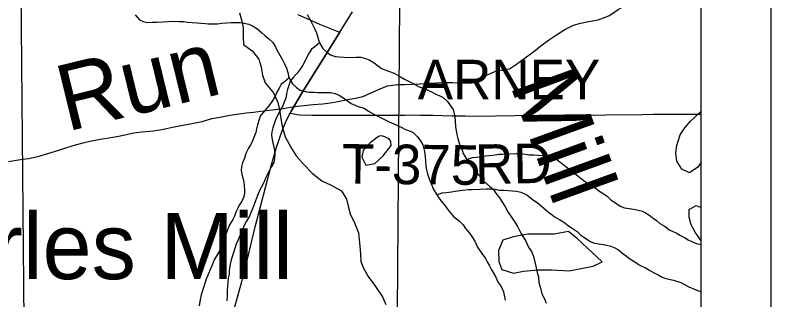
# Model space of a CAD drawing. Extents: x -21.1 to 50.3, y -4.9 to 22.1.
# Drawn here: x 7.916 to 9, y 17.651 to 18.059 of the extents above; entities that cross this region are included whole.
import ezdxf

# ---------------------------------------------------------------- set-up
doc = ezdxf.new("R2010")
doc.units = 0
for name, color, linetype in [('GM_X_Corporation', 7, 'Continuous'), ('GM_X_County', 7, 'Continuous'), ('GM_X_County_Road', 7, 'Continuous'), ('GM_X_Major_Lake', 7, 'Continuous'), ('GM_X_Major_Lake_Text', 7, 'Continuous'), ('GM_X_Minor_Lake', 7, 'Continuous'), ('GM_X_Minor_River', 7, 'Continuous'), ('GM_X_Minor_River_Text', 7, 'Continuous'), ('GM_X_Rail_Line_Text', 7, 'Continuous'), ('GM_X_Section', 7, 'Continuous'), ('GM_X_Township_Road', 7, 'Continuous'), ('GM_X_Township_Road_Text', 7, 'Continuous'), ('SH_Cut_Line', 7, 'Continuous'), ('SH_Data', 7, 'Continuous')]:
    doc.layers.add(name, color=color, linetype=linetype)

msp = doc.modelspace()

# ---------------------------------------------------------------- linework, layer by layer
at = {"layer": 'GM_X_Corporation'}
msp.add_lwpolyline([(8.9, 17.418), (8.9, 18.4235), (7.9213, 18.4125), (7.9303, 17.4089)], close=True, dxfattribs=at)
at = {"layer": 'GM_X_County'}
msp.add_lwpolyline([(8.9, 14.7464), (8.9, 20.9), (2.1, 20.9), (2.1, 14.1), (8.8932, 14.1)], dxfattribs=at)
at = {"layer": 'GM_X_County_Road'}
for points in [[(8.3818, 18.035), (8.4, 18.0643)], [(8.3107, 17.9188), (8.3121, 17.9215), (8.3278, 17.9484), (8.3572, 17.9959), (8.377, 18.0274), (8.3818, 18.035)], [(8.2266, 17.6235), (8.2411, 17.6773), (8.2487, 17.7073), (8.2605, 17.7556), (8.2721, 17.8008), (8.2833, 17.8429), (8.291, 17.8697), (8.2991, 17.8933), (8.305, 17.9077), (8.3107, 17.9188)]]:
    msp.add_lwpolyline(points, dxfattribs=at)
at = {"layer": 'GM_X_Major_Lake'}
for points in [[(8.2379, 18.0629), (8.2406, 18.0527), (8.2432, 18.0417), (8.2432, 18.0284), (8.2436, 18.017), (8.2561, 18.0083), (8.2655, 17.9962), (8.2689, 17.9848), (8.2708, 17.9731), (8.2746, 17.9624), (8.2864, 17.948), (8.2928, 17.934), (8.2951, 17.9241), (8.2973, 17.9105), (8.2996, 17.8976), (8.3034, 17.8847), (8.3121, 17.8691), (8.3189, 17.8574), (8.3299, 17.8452), (8.342, 17.8327), (8.356, 17.8217), (8.3693, 17.8153), (8.3841, 17.8073), (8.3913, 17.7952), (8.3935, 17.7853), (8.3966, 17.774), (8.403, 17.7611), (8.4083, 17.747), (8.4102, 17.7326), (8.4113, 17.7167), (8.4121, 17.7057), (8.4155, 17.6962), (8.4223, 17.6841), (8.4329, 17.67), (8.4431, 17.6549), (8.4477, 17.6439)], [(8.9, 17.8485), (8.8951, 17.8411), (8.8833, 17.8332), (8.8723, 17.8382), (8.8651, 17.85), (8.8637, 17.8618), (8.8652, 17.8724), (8.8698, 17.8876), (8.8767, 17.8975), (8.8847, 17.9073), (8.8973, 17.9186), (8.9, 17.9214)], [(8.4549, 17.8778), (8.4545, 17.8792), (8.4532, 17.8809), (8.4513, 17.8824), (8.4491, 17.8834), (8.4462, 17.8845), (8.4436, 17.8856), (8.4399, 17.8862), (8.4373, 17.8853)], [(8.4373, 17.8853), (8.4251, 17.8763), (8.4151, 17.865), (8.4131, 17.8555), (8.4191, 17.8441), (8.432, 17.8463), (8.4438, 17.8575), (8.4553, 17.8722), (8.4549, 17.8778)], [(8.9, 17.7354), (8.8979, 17.7385), (8.8914, 17.748), (8.8857, 17.7586), (8.8827, 17.7696), (8.8827, 17.7803), (8.893, 17.786), (8.9, 17.7832)]]:
    msp.add_lwpolyline(points, dxfattribs=at)
at = {"layer": 'GM_X_Minor_Lake'}
for points in [[(8.7223, 17.739), (8.7099, 17.749), (8.6893, 17.7451), (8.6681, 17.7449), (8.6514, 17.7451), (8.6305, 17.7411), (8.6156, 17.7363), (8.6094, 17.7216), (8.6096, 17.7056), (8.614, 17.6942), (8.6307, 17.6891), (8.6451, 17.692), (8.666, 17.6937), (8.6858, 17.6938), (8.7108, 17.6924), (8.7302, 17.6964), (8.745, 17.6993), (8.758, 17.7053)], [(8.758, 17.7053), (8.7223, 17.739)]]:
    msp.add_lwpolyline(points, dxfattribs=at)
at = {"layer": 'GM_X_Minor_River'}
for points in [[(8.6826, 18.0245), (8.6925, 18.0312), (8.7044, 18.0386), (8.7167, 18.0449), (8.727, 18.0478), (8.7388, 18.0502), (8.7525, 18.0527), (8.7678, 18.0585), (8.7812, 18.0675), (8.7943, 18.0752), (8.8076, 18.0807), (8.8206, 18.0828), (8.832, 18.083), (8.8456, 18.0824), (8.8555, 18.0827), (8.8677, 18.0836), (8.8772, 18.0846), (8.8883, 18.0875), (8.8978, 18.0927), (8.9, 18.0944)], [(8.0884, 18.0596), (8.0946, 18.0524), (8.0995, 18.0502), (8.1052, 18.049), (8.1128, 18.0491), (8.1193, 18.0491), (8.1281, 18.0496), (8.1361, 18.0504), (8.1425, 18.0508), (8.1509, 18.0504), (8.1578, 18.0501), (8.1627, 18.0494), (8.1772, 18.0483), (8.1825, 18.048), (8.1886, 18.0472), (8.1936, 18.0469), (8.2065, 18.0469), (8.2126, 18.0477), (8.219, 18.0482), (8.2259, 18.0486), (8.232, 18.049), (8.2388, 18.0486), (8.2445, 18.0479), (8.251, 18.0464), (8.2564, 18.0438), (8.2625, 18.04), (8.2698, 18.034), (8.2747, 18.0298), (8.2797, 18.0253), (8.2851, 18.0204), (8.2889, 18.0147), (8.2916, 18.0098), (8.2958, 18.0018), (8.2993, 17.9954), (8.3024, 17.9897), (8.3051, 17.9833), (8.307, 17.9768), (8.3082, 17.9719), (8.3105, 17.9666), (8.3139, 17.9609), (8.3197, 17.9556), (8.325, 17.9519), (8.3319, 17.9496), (8.3376, 17.9489), (8.3448, 17.9486), (8.3502, 17.9482), (8.3616, 17.9483), (8.3688, 17.9483), (8.3753, 17.9468), (8.3806, 17.9446), (8.3875, 17.9404), (8.3982, 17.9325), (8.4081, 17.9284), (8.4165, 17.9258), (8.423, 17.9216), (8.4314, 17.9167), (8.4429, 17.9111), (8.4524, 17.9062), (8.4593, 17.9036), (8.4707, 17.8983), (8.4761, 17.8953), (8.4818, 17.8931), (8.4868, 17.8908), (8.4925, 17.8852), (8.4963, 17.8802), (8.5009, 17.8734), (8.5033, 17.8636), (8.5041, 17.8564), (8.5045, 17.8491), (8.5053, 17.8427), (8.5061, 17.8374), (8.5076, 17.8317), (8.5107, 17.8218), (8.5134, 17.8169), (8.5154, 17.8101), (8.5207, 17.8017), (8.5273, 17.7923), (8.5326, 17.7855), (8.5376, 17.779), (8.5449, 17.7703), (8.5533, 17.7636), (8.5587, 17.7586), (8.5621, 17.7533), (8.5675, 17.7465), (8.5709, 17.7416), (8.5752, 17.7348), (8.5794, 17.7265), (8.5855, 17.7174), (8.5905, 17.7102), (8.5932, 17.7053)], [(8.3349, 18.0603), (8.3391, 18.0524), (8.3426, 18.0459), (8.3456, 18.0402), (8.3483, 18.0338), (8.3503, 18.0274), (8.3515, 18.0224), (8.3538, 18.0171), (8.3572, 18.0114), (8.363, 18.0061), (8.3683, 18.0024), (8.3752, 18.0001), (8.3809, 17.9994), (8.3881, 17.9991), (8.3935, 17.9987), (8.4049, 17.9988), (8.4121, 17.9988), (8.4186, 17.9973), (8.4239, 17.9951), (8.4308, 17.9909), (8.4415, 17.983), (8.4514, 17.9789), (8.4598, 17.9763), (8.4663, 17.9721), (8.4747, 17.9673), (8.4862, 17.9616), (8.4957, 17.9567), (8.5026, 17.9541), (8.514, 17.9489), (8.5194, 17.9459), (8.5251, 17.9436), (8.53, 17.9413), (8.5358, 17.9357), (8.5396, 17.9308), (8.5442, 17.924), (8.5466, 17.9141), (8.5474, 17.9069), (8.5478, 17.8997), (8.5486, 17.8932), (8.5494, 17.8879), (8.5509, 17.8822), (8.554, 17.8723), (8.5567, 17.8674), (8.5587, 17.8606), (8.564, 17.8523), (8.5706, 17.8428), (8.5759, 17.836), (8.5809, 17.8296), (8.5882, 17.8209), (8.5966, 17.8141), (8.602, 17.8092), (8.6054, 17.8039), (8.6108, 17.7971), (8.6142, 17.7921), (8.6185, 17.7853), (8.6227, 17.777), (8.6288, 17.7679), (8.6338, 17.7607), (8.6365, 17.7558)], [(7.9065, 17.8494), (7.9237, 17.8522), (7.9351, 17.8535), (7.9484, 17.8564), (7.9629, 17.8607), (7.9789, 17.8658), (7.99, 17.8694), (8.0026, 17.873), (8.0137, 17.8763), (8.0232, 17.8784), (8.0384, 17.8812), (8.0506, 17.8833), (8.0617, 17.8854), (8.0716, 17.8872), (8.0864, 17.8903), (8.0979, 17.8921), (8.1138, 17.8933), (8.1264, 17.8951), (8.1416, 17.8986), (8.1542, 17.9011), (8.1672, 17.9036), (8.1843, 17.9067), (8.1984, 17.9111), (8.2098, 17.9128), (8.2239, 17.9156), (8.2342, 17.9173), (8.2472, 17.9191), (8.2578, 17.92), (8.2685, 17.9214), (8.2852, 17.9234), (8.3004, 17.9255), (8.3111, 17.9272), (8.321, 17.9289), (8.3305, 17.9299), (8.3435, 17.9313), (8.3575, 17.9322), (8.3686, 17.9335), (8.3788, 17.9353), (8.3926, 17.9381), (8.404, 17.9402), (8.4147, 17.9427), (8.4265, 17.9479), (8.4372, 17.9526), (8.4502, 17.9578), (8.4643, 17.9598), (8.4746, 17.96), (8.486, 17.9602), (8.4958, 17.9609), (8.5091, 17.9618), (8.5206, 17.9624), (8.5339, 17.9629), (8.5437, 17.9628), (8.5547, 17.9622), (8.5676, 17.9617), (8.5817, 17.9637), (8.5917, 17.9727), (8.6048, 17.979), (8.6158, 17.9807), (8.6253, 17.9824), (8.6353, 17.9891), (8.6495, 17.9996), (8.6599, 18.0074), (8.6703, 18.0156), (8.6826, 18.0245)], [(8.3526, 18.0198), (8.3458, 18.014), (8.3409, 18.0106), (8.3378, 18.0053), (8.3345, 17.9992), (8.3322, 17.9938), (8.3288, 17.9877), (8.3247, 17.9816), (8.3205, 17.9763), (8.3148, 17.9698), (8.3107, 17.9648), (8.3092, 17.9599), (8.3069, 17.9527), (8.3054, 17.9469), (8.3047, 17.9416), (8.3017, 17.9344), (8.2998, 17.9291), (8.2968, 17.9237), (8.2942, 17.9188), (8.2904, 17.9115), (8.2882, 17.9047), (8.2855, 17.8978), (8.284, 17.8921), (8.2837, 17.8872), (8.2845, 17.8811), (8.2857, 17.8762), (8.2872, 17.8701), (8.288, 17.8652), (8.2884, 17.8599), (8.2881, 17.8534), (8.287, 17.8481), (8.2839, 17.842), (8.2809, 17.837), (8.2783, 17.8321), (8.276, 17.8271), (8.2738, 17.8214), (8.2715, 17.8165), (8.267, 17.8088), (8.2636, 17.8005), (8.2606, 17.7928), (8.2587, 17.7875), (8.2572, 17.7826), (8.2546, 17.7769), (8.252, 17.7708), (8.2478, 17.7635), (8.2448, 17.7586), (8.2418, 17.751), (8.2396, 17.746), (8.2358, 17.7369), (8.2332, 17.7308), (8.2309, 17.7232), (8.2261, 17.7083), (8.2246, 17.7019), (8.2231, 17.6927), (8.2228, 17.6878), (8.2216, 17.6817), (8.2213, 17.676), (8.2206, 17.6703), (8.2202, 17.6635), (8.2203, 17.6559), (8.2199, 17.6494)], [(8.3093, 17.9693), (8.3025, 17.9635), (8.2976, 17.9601), (8.2946, 17.9547), (8.2912, 17.9486), (8.2889, 17.9433), (8.2855, 17.9372), (8.2814, 17.9311), (8.2772, 17.9258), (8.2715, 17.9193), (8.2674, 17.9143), (8.2659, 17.9094), (8.2636, 17.9021), (8.2621, 17.8964), (8.2614, 17.8911), (8.2584, 17.8839), (8.2565, 17.8785), (8.2535, 17.8732), (8.2509, 17.8683), (8.2471, 17.861), (8.2449, 17.8542), (8.2422, 17.8473), (8.2408, 17.8416), (8.2404, 17.8367), (8.2412, 17.8306), (8.2424, 17.8257), (8.2439, 17.8196), (8.2447, 17.8147), (8.2451, 17.8093), (8.2448, 17.8029), (8.2437, 17.7976), (8.2406, 17.7915), (8.2376, 17.7865), (8.235, 17.7816), (8.2327, 17.7766), (8.2305, 17.7709), (8.2282, 17.7659), (8.2237, 17.7583), (8.2203, 17.7499), (8.2173, 17.7423), (8.2154, 17.737), (8.214, 17.7321), (8.2113, 17.7263), (8.2087, 17.7202), (8.2045, 17.713), (8.2015, 17.7081), (8.1985, 17.7004), (8.1963, 17.6955), (8.1925, 17.6863), (8.1899, 17.6803), (8.1876, 17.6726), (8.1828, 17.6578), (8.1813, 17.6513), (8.1798, 17.6422)], [(8.5642, 17.8521), (8.572, 17.855), (8.5777, 17.8554), (8.5853, 17.8562), (8.5907, 17.8573), (8.6013, 17.8585), (8.6097, 17.8597), (8.615, 17.8598), (8.6257, 17.8602), (8.6348, 17.8606), (8.6416, 17.8607), (8.6477, 17.8599), (8.6535, 17.8588), (8.6599, 17.8589), (8.6725, 17.8578), (8.6786, 17.8571), (8.6847, 17.856), (8.6931, 17.8522), (8.7015, 17.8454), (8.708, 17.8409), (8.7137, 17.836), (8.721, 17.83), (8.726, 17.8262), (8.734, 17.8202), (8.7416, 17.8156), (8.7477, 17.8119), (8.7531, 17.8073), (8.7581, 17.8043), (8.7653, 17.7994), (8.771, 17.7938), (8.7772, 17.79), (8.784, 17.7851), (8.7901, 17.7829), (8.8, 17.7814), (8.8058, 17.7803), (8.8138, 17.7784), (8.8187, 17.7766), (8.8248, 17.7728), (8.831, 17.7679), (8.8359, 17.7645), (8.8409, 17.7603), (8.8482, 17.7558), (8.8543, 17.7513), (8.8592, 17.749), (8.8642, 17.7468), (8.8695, 17.7434), (8.876, 17.74), (8.8814, 17.737), (8.8875, 17.734), (8.8928, 17.7318), (8.9, 17.7303)], [(8.5209, 17.8016), (8.5287, 17.8044), (8.5344, 17.8049), (8.542, 17.8057), (8.5474, 17.8068), (8.558, 17.808), (8.5664, 17.8092), (8.5717, 17.8092), (8.5824, 17.8097), (8.5915, 17.8101), (8.5984, 17.8102), (8.6044, 17.8094), (8.6102, 17.8083), (8.6166, 17.8084), (8.6292, 17.8073), (8.6353, 17.8066), (8.6414, 17.8055), (8.6498, 17.8017), (8.6582, 17.7949), (8.6647, 17.7904), (8.6704, 17.7855), (8.6777, 17.7794), (8.6827, 17.7757), (8.6907, 17.7696), (8.6983, 17.7651), (8.7044, 17.7614), (8.7098, 17.7568), (8.7148, 17.7538), (8.722, 17.7489), (8.7278, 17.7432), (8.7339, 17.7395), (8.7408, 17.7346), (8.7469, 17.7323), (8.7568, 17.7309), (8.7625, 17.7298), (8.7705, 17.7279), (8.7754, 17.726), (8.7815, 17.7223), (8.7877, 17.7174), (8.7926, 17.714), (8.7976, 17.7098), (8.8049, 17.7053), (8.811, 17.7008), (8.8159, 17.6985), (8.8209, 17.6963), (8.8262, 17.6929), (8.8327, 17.6895), (8.8381, 17.6865), (8.8442, 17.6835), (8.8495, 17.6812), (8.8603, 17.679)], [(8.6365, 17.7558), (8.6396, 17.7501), (8.6423, 17.7452), (8.6484, 17.735), (8.6523, 17.7262), (8.6565, 17.7202), (8.6596, 17.713), (8.6623, 17.7008), (8.665, 17.6898), (8.6666, 17.6838), (8.6674, 17.6758), (8.6701, 17.6663), (8.6717, 17.6595), (8.6752, 17.6523), (8.6779, 17.6462)], [(8.5932, 17.7053), (8.5963, 17.6996), (8.599, 17.6947), (8.6051, 17.6844), (8.609, 17.6757), (8.6132, 17.6697), (8.6163, 17.6625), (8.619, 17.6503)], [(8.8603, 17.679), (8.8707, 17.6756), (8.8821, 17.6695), (8.8916, 17.6658), (8.9, 17.6623)]]:
    msp.add_lwpolyline(points, dxfattribs=at)
at = {"layer": 'GM_X_Rail_Line_Text'}
msp.add_lwpolyline([(8.9, 16.4052), (8.9, 20.435)], dxfattribs=at)
at = {"layer": 'GM_X_Section'}
msp.add_lwpolyline([(7.4621, 18.1346), (8.4678, 18.1394), (8.46, 17.1311), (8.3964, 17.1315), (7.4753, 17.1323)], close=True, dxfattribs=at)
at = {"layer": 'GM_X_Township_Road'}
for points in [[(8.3217, 18.0605), (8.3527, 18.0465), (8.3671, 18.0407), (8.3789, 18.0361), (8.3818, 18.035)], [(8.3818, 18.035), (8.377, 18.0274), (8.3572, 17.9959), (8.3278, 17.9484), (8.3121, 17.9215), (8.3107, 17.9188)], [(8.3107, 17.9188), (8.3162, 17.9176), (8.3205, 17.9167), (8.3246, 17.9163), (8.3415, 17.9159), (8.3694, 17.9159), (8.3974, 17.9158), (8.4191, 17.9156), (8.4377, 17.9157), (8.4563, 17.9158), (8.4749, 17.9159), (8.4873, 17.9161), (8.4966, 17.916), (8.5152, 17.9156), (8.5431, 17.915), (8.5617, 17.9147), (8.5804, 17.9145), (8.6052, 17.9147), (8.6331, 17.9152), (8.6672, 17.9159), (8.692, 17.916), (8.7137, 17.9157), (8.7292, 17.9157), (8.7633, 17.9162), (8.8161, 17.9169), (8.8316, 17.9171), (8.847, 17.9171), (8.8778, 17.9171), (8.9, 17.9174)]]:
    msp.add_lwpolyline(points, dxfattribs=at)
at = {"layer": 'SH_Cut_Line'}
msp.add_lwpolyline([(8.9, 16.4052), (8.9, 20.9), (2.1, 20.9)], dxfattribs=at)
at = {"layer": 'SH_Data'}
msp.add_line((9, 21), (9, 14), dxfattribs=at)

# ---------------------------------------------------------------- texts
at = {"layer": 'GM_X_Major_Lake_Text'}
for s, height, rotation, p in [('Mill', 0.09473, 289.9962, (8.6253, 17.9601)), ('Charles Mill', 0.094718, 359.9981, (7.6527, 17.6805))]:
    msp.add_text(s, height=height, rotation=rotation, dxfattribs=at).set_placement(p)
at = {"layer": 'GM_X_Minor_River_Text'}
msp.add_text('Run', height=0.09472, rotation=13.7754, dxfattribs=at).set_placement((7.99, 17.892))
at = {"layer": 'GM_X_Township_Road_Text'}
for s, rotation, p in [('ARNEY', 0.0056, (8.4935, 17.9384)), ('RD', 0.9611, (8.5761, 17.8169)), ('T-375', 359.4489, (8.3845, 17.8176))]:
    msp.add_text(s, height=0.05682, rotation=rotation, dxfattribs=at).set_placement(p)

doc.saveas('drawing.dxf')
